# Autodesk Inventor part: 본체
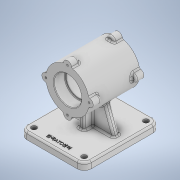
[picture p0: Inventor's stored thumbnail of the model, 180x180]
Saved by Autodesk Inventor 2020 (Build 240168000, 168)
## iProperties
Created: 2022-11
Part Number: 본체
Material: 일반
Document SubType Name: Modeling
Designer: owner
Density: 1 g/cm^3
Appearance: 기본값
Mass: 450.106 g
Surface Area: 797.121 cm^2
Volume: 450.106 cm^3
Author: owner
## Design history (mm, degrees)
sketch "스케치1"
  geometry: L1 (-55, 65)-(55, 65); L2 (55, 65)-(55, -65); L3 (55, -65)-(-55, -65); L4 (-55, -65)-(-55, 65); L5 (-55, 65)-(55, -65); L6 (55, 65)-(-55, -65); 1 further point
  constraints: 12 end point, 2 midpoint, 2 parallel, 1 horizontal, 1 perpendicular
  dimensions: "d0" = 110 distance of L1.start L1.end; "d1" = 130 distance of L3.end L1.start
extrude "돌출1" new body sketch "스케치1" distance "d2" = 12; taper "d3" = 0 deg
node "작업 평면1"
sketch "스케치2"
  geometry: L1 (0, 0)-(110, 0) reference; C1 r 37 at (55, 82); 2 further points
  constraints: 1 centre point, 1 midpoint, 1 vertical alignment
  dimensions: "d5" = 74 diameter of C1; "d44" = 82 distance from line of L1 C1.centre
extrude "돌출2" join sketch "스케치2" stored distance "d6" = 87; taper "d7" = 0 deg
sketch "스케치3"
  geometry: C1 r 37 at (0, 0) reference; 2 further points
  constraints: 1 coincident
hole "구멍1" sketch "스케치3" at (0, 0) diameter "d8" = 42; stored, may be unused: countersink angle "d12" = 90 deg, drill point angle "d14" = 0 deg; dims "d9" = 12, "d10" = 14, "d11" = 4, "d13" = 17.1
sketch "스케치4"
  geometry: C1 r 21 at (0, 0) reference; 2 further points
  constraints: 1 coincident
hole "구멍2" sketch "스케치4" at (0, 0) diameter "d15" = 47; stored, may be unused: countersink angle "d19" = 90 deg, drill point angle "d21" = 0 deg; dims "d16" = 12, "d17" = 14, "d18" = 4, "d20" = 19
sketch "스케치5"
  geometry: C1 r 21 at (0, 0) reference; 2 further points
  constraints: 1 coincident
hole "구멍3" sketch "스케치5" at (0, 0) diameter "d22" = 47; stored, may be unused: countersink angle "d26" = 90 deg, drill point angle "d28" = 0 deg; dims "d23" = 12, "d24" = 14, "d25" = 4, "d27" = 19
sketch "스케치6"
  geometry: C1 r 7 at (0, 37); 3 further points
  constraints: 3 vertical alignment, 1 centre point, 2 other
  dimensions: "d29" = 14 diameter of C1
extrude "돌출3" join sketch "스케치6" distance "d30" = 14; taper "d31" = 0 deg
sketch "스케치7"
  geometry: A1 r 37 centre (55, 82) between (48.031, 118.338) and (61.969, 118.338) reference; A2 r 7 centre (55, 119) between (61.969, 118.338) and (48.031, 118.338) reference; A3 r 37 centre (55, 82) between (61.969, 118.338) and (48.031, 118.338) reference; 2 further points
  constraints: 1 coincident
hole "구멍4" sketch "스케치7" at (55, 119) diameter "d32" = 3.242; stored, may be unused: countersink angle "d36" = 90 deg, drill point angle "d38" = 118 deg; dims "d33" = 8, "d34" = 14, "d35" = 4, "d37" = 10
fillet "모깎기1" dims "d39" = 3
fillet "모깎기2" dims "d40" = 3
node "작업 평면2"
sketch "스케치10"
  geometry: L1 (29.664, 55.036)-(14, 12); L2 (80.336, 55.036)-(96, 12); L3 (0, 12)-(110, 12) reference; L4 (0, 0)-(0, 12) reference; L5 (29.664, 55.036)-(80.336, 55.036); C1 r 1.621 at (92, 82) reference; C2 r 1.621 at (55, 45) reference; C3 r 1.621 at (18, 82) reference; C4 r 1.621 at (55, 119) reference; C5 r 23.5 at (55, 82) reference; A1 r 37 centre (55, 82) between (90.862, 91.104) and (64.104, 117.863) reference; A2 r 3 centre (64.842, 120.77) between (61.889, 120.239) and (64.104, 117.863) reference; A3 r 7 centre (55, 119) between (61.889, 120.239) and (48.111, 120.239) reference; A4 r 3 centre (45.158, 120.77) between (45.896, 117.863) and (48.111, 120.239) reference; A5 r 37 centre (55, 82) between (45.896, 117.863) and (19.137, 91.104) reference; A6 r 3 centre (16.23, 91.842) between (16.761, 88.889) and (19.137, 91.104) reference; A7 r 7 centre (18, 82) between (16.761, 88.889) and (16.761, 75.111) reference; A8 r 3 centre (16.23, 72.158) between (19.137, 72.896) and (16.761, 75.111) reference; A9 r 37 centre (55, 82) between (19.137, 72.896) and (45.896, 46.138) reference; A10 r 3 centre (45.158, 43.23) between (48.111, 43.761) and (45.896, 46.138) reference; A11 r 7 centre (55, 45) between (48.111, 43.761) and (61.889, 43.761) reference; A12 r 3 centre (64.842, 43.23) between (64.104, 46.138) and (61.889, 43.761) reference; A13 r 37 centre (55, 82) between (64.104, 46.138) and (90.862, 72.896) reference; A14 r 3 centre (93.77, 72.158) between (93.239, 75.111) and (90.862, 72.896) reference; A15 r 7 centre (92, 82) between (93.239, 75.111) and (93.239, 88.889) reference; A16 r 3 centre (93.77, 91.842) between (90.862, 91.104) and (93.239, 88.889) reference; A17 r 37 centre (55, 82) between (19.137, 72.896) and (45.896, 46.138) reference; A18 r 37 centre (55, 82) between (64.104, 46.138) and (90.862, 72.896) reference; A19 r 37 centre (55, 82) between (90.862, 91.104) and (64.104, 117.863) reference; A20 r 37 centre (55, 82) between (57.543, 118.913) and (52.457, 118.913) reference; A21 r 37 centre (55, 82) between (45.896, 117.863) and (19.137, 91.104) reference; A22 r 37 centre (55, 82) between (18.087, 84.543) and (18.087, 79.457) reference; A23 r 37 centre (55, 82) between (19.137, 72.896) and (45.896, 46.138) reference; A24 r 37 centre (55, 82) between (52.457, 45.088) and (57.543, 45.088) reference; A25 r 37 centre (55, 82) between (64.104, 46.138) and (90.862, 72.896) reference; A26 r 37 centre (55, 82) between (91.912, 79.457) and (91.912, 84.543) reference; A27 r 37 centre (55, 82) between (64.104, 46.138) and (90.862, 72.896) reference; A28 r 37 centre (55, 82) between (52.457, 45.088) and (57.543, 45.088) reference; A29 r 37 centre (55, 82) between (19.137, 72.896) and (45.896, 46.138) reference; A30 r 37 centre (55, 82) between (18.087, 84.543) and (18.087, 79.457) reference; A31 r 37 centre (55, 82) between (45.896, 117.863) and (19.137, 91.104) reference; A32 r 37 centre (55, 82) between (57.543, 118.913) and (52.457, 118.913) reference; A33 r 37 centre (55, 82) between (90.862, 91.104) and (64.104, 117.863) reference; A34 r 37 centre (55, 82) between (91.912, 79.457) and (91.912, 84.543) reference; 23 further points
  constraints: 6 end point, 2 point on circle, 2 point on line, 16 other
  dimensions: "d47" = 110 deg angle of L3 L1; "d48" = 110 deg angle of L3 L2; "d49" = 14 distance of L3.end L2.end; "d50" = 14 distance from line of L1.end L4
extrude "돌출4" join sketch "스케치10" stored distance "d51" = 10; taper "d52" = 0 deg
sketch "스케치11"
  geometry: L1 (45, -31.5)-(45, 21.5) reference; L2 (45, 15)-(12, 15); L3 (12, -65)-(12, 65) reference; L4 (45, -25)-(12, -25); L5 (12, -25)-(12, 15); L6 (12, 0)-(12, -10) reference; L7 (55.036, 0)-(12, 0) reference; L8 (55.036, -10)-(55.036, 0) reference; L9 (12, -10)-(55.036, -10) reference; L10 (12, 0)-(12, -10) reference; 4 further points
  constraints: 6 end point, 5 midpoint, 4 point on line, 1 coincident, 1 collinear, 1 horizontal, 1 perpendicular
  dimensions: "d53" = 40 distance between parallel lines of L4 L2
feature "리브1" sketch "스케치11" dims "d54" = 1, "d55" = 10, "d56" = 0, "d57" = 0, "d58" = 1, "d59" = 1
fillet "모깎기3" dims "d60" = 12
fillet "모깎기4" dims "d61" = 3
sketch "스케치12" dims "d28" = 0
  geometry: A1 r 9 centre (-43, -53) between (-52, -53) and (-43, -62) reference; 2 further points
  constraints: 1 coincident
hole "구멍5" sketch "스케치12" at (-43, -53) diameter "d62" = 9; stored, may be unused: drill point angle "d28" = 0 deg, countersink angle "d66" = 90 deg, drill point angle "d68" = 0 deg; dims "d63" = 8, "d64" = 14, "d65" = 4, "d67" = 10
sketch "스케치13"
  geometry: L1 (43, -62)-(-43, -62) reference; L2 (41, 10)-(41, 0) reference; 4 further points
  constraints: 1 midpoint, 1 vertical alignment, 1 other
  dimensions: "d69" = 58 vertical distance of point (0, -52.949) point (77.365, 5.051)
feature "엠보싱1" sketch "스케치13" dims "d0" = 110, "d1" = 130, "d70" = 0.5, "d71" = 0
chamfer "모따기1" distance "d72" = 1; stored, may be unused: second distance "d73" = 2, angle "d74" = 45 deg
fillet "모깎기5" dims "d75" = 1
fillet "모깎기8" dims "d78" = 3
fillet "모깎기9" dims "d79" = 3
node "솔리드1"
pattern_circular "원형 패턴1" dims "d42" = 360 deg
mirror "미러1"
mirror "미러2"
mirror "미러3"
node "투영된 루프1"
node "투영된 루프2"
node "투영된 루프3"
feature "A9D066F2-1C7D-4E18-AEED-F7BC21143FA4" dims "d8" = 42, "d9" = 12, "d10" = 14, "d11" = 4, "d12" = 90 deg, "d13" = 17.1, "d14" = 0
